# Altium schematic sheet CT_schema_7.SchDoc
size 277 x 170 mm
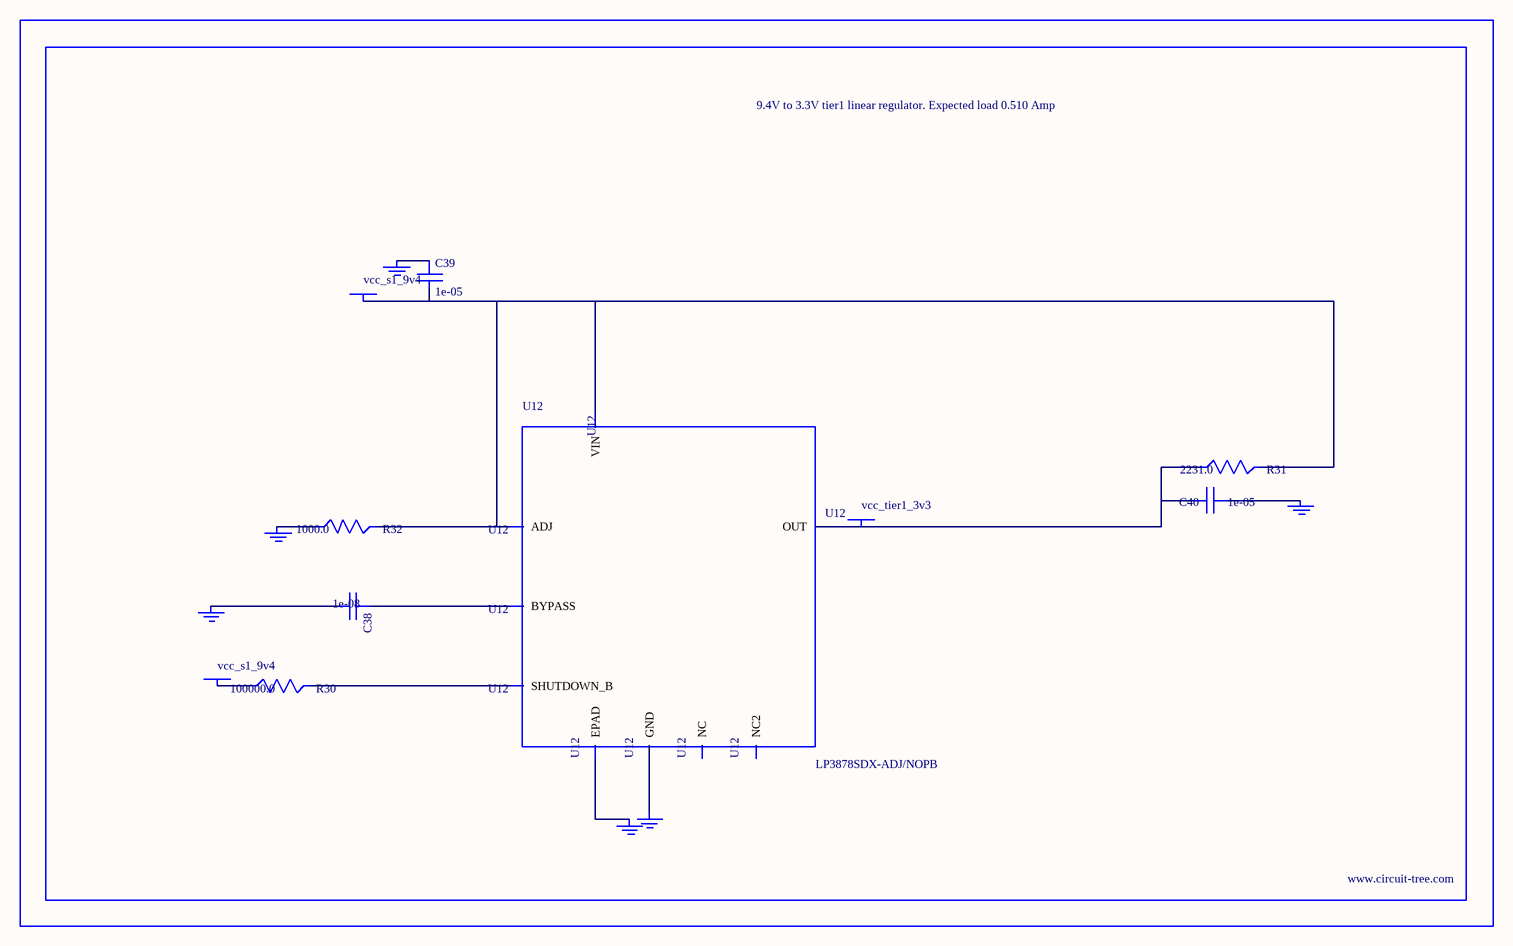
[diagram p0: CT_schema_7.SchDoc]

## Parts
BORDER6  (no value)
C38  1e-08  [C0402]
C39  1e-05  [C1206]
C40  1e-05  [C1210]
GND_INSTANCE_6_0  (no value)
GND_INSTANCE_6_1  (no value)
GND_INSTANCE_6_2  (no value)
GND_INSTANCE_6_3  (no value)
GND_INSTANCE_6_4  (no value)
GND_INSTANCE_6_5  (no value)
POWER_INSTANCE_6_0  vcc_s1_9v4
POWER_INSTANCE_6_1  vcc_s1_9v4
POWER_INSTANCE_6_2  vcc_tier1_3v3
R30  100000.0  [R0603]
R31  2231.0  [R0603]
R32  1000.0  [R0603]
U12  LP3878SDX-ADJ/NOPB  [WSON-8]

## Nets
NetC38_1: C38.1 U12.1(BYPASS)
NetC38_2: C38.2 GND_INSTANCE_6_0.0(GND)
NetC39_1: C39.1 GND_INSTANCE_6_1.0(GND)
NetC39_2: C39.2 POWER_INSTANCE_6_0.0(PWR) R31.2 R32.2 U12.4(VIN) U12.6(ADJ)
NetC40_1: C40.1 GND_INSTANCE_6_2.0(GND)
NetC40_2: C40.2 POWER_INSTANCE_6_2.0(PWR) R31.1 U12.5(OUT)
NetGND_INSTANCE_6_3_0: GND_INSTANCE_6_3.0(GND) R32.1
NetGND_INSTANCE_6_4_0: GND_INSTANCE_6_4.0(GND) U12.PAD(EPAD)
NetGND_INSTANCE_6_5_0: GND_INSTANCE_6_5.0(GND) U12.3(GND)
NetPOWER_INSTANCE_6_1_0: POWER_INSTANCE_6_1.0(PWR) R30.1
NetR30_2: R30.2 U12.8(SHUTDOWN_B)

Not connected (* = marked no-connect by the designer): U12 2(NC) 7(NC2)

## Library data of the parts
BORDER6 = BORDER_PAGE6
C38 = C0402C103K3RAC
C39 = C1206C106K3RACTU
C40 = GRM32DR61E106MA12L
GND_INSTANCE_6_0-GND_INSTANCE_6_5 = GND
POWER_INSTANCE_6_0-POWER_INSTANCE_6_2 = PWR
R30 = RC0603JR-07100KL
R31 = R31
R32 = RC0603JR-071KL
